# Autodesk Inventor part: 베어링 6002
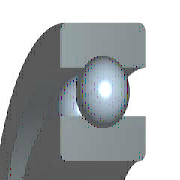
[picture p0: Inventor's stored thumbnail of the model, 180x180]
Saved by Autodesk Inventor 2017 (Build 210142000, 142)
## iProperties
IsCustomPart: 0
Created: 2012-02
Part Number: 베어링 6002
Material: 강철, 연강
Description: 깊은 그루브 볼 베어링
Document SubType Name: Modeling
Standard: KS B 2023
Designer: mduedu
Standards Organization: KS
Language: ko-KR
Size Designation: 6002 - 15 x 32 x 9
Categories: <MemberInstance><Categories><Category DisplayName="샤프트 부품" InternalName="7f7aeb1f-a693-4053-b835-cee3144e0d98" Mnemonic="SHFT"><Category DisplayName="베어링" Inter
Density: 7.86 g/cm^3
Mass: 29.8124 g
Surface Area: 39.9079 cm^2
Volume: 3.79293 cm^3
Appearance: 노란색
Author: mduedu
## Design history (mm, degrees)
sketch "스케치" dims "d0" = 4.42 (= -0.26 x WD + 0.26 x BD)
  geometry: L1 (2.29, 11.75)-(6.71, 11.75); L2 (4.5, 11.75)-(4.5, 9.54); L3 (4.5, 11.75)-(4.5, 13.96); L4 (2.858, 10.271)-(0, 10.271); L5 (0, 7.5)-(9, 7.5); L6 (2.858, 13.229)-(0, 13.229); L7 (0, 16)-(9, 16); L8 (9, 7.5)-(9, 10.271); L9 (6.142, 10.271)-(9, 10.271); L10 (6.142, 13.229)-(9, 13.229); L11 (9, 16)-(9, 13.229); L12 (-1.4, 0)-(8.4, 0) reference; L13 (0, -0.3)-(0, 5.3) reference
  constraints: 22 end point, 4 point on line, 2 collinear, 2 perpendicular, 2 symmetric about line, 1 midpoint, 1 parallel, 14 other
  dimensions: "d9" = 15 diameter of L5 L12 (= WD); "d11" = 32 diameter of L7 L12 (= BD); "d12" = 9 distance between parallel lines of L8 L13 (= KB); "d13" = 20.542 diameter of L9 L12 (= 0.326 x BD + 0.674 x WD)
revolve "본체" stored, may be unused: angle "d6" = 90 deg
revolve "볼" stored, may be unused: angle "d7" = 90 deg
pattern_circular "IDS_ARRAYBALL[SIMPL:T]" dims angle "d3" = 360 deg
body "Solid1"
fillet "모깎기1" dims "d1" = 0.3 (= KRS)
other parameters: "WD" = 15 [user parameter; used in 5 equation terms], "BD" = 32 [user parameter; used in 5 equation terms], "KB" = 9 [user parameter; used in 1 equation term], "KRS" = 0.3 [user parameter; used in 1 equation term], "d4" = 0, "d5" = 0, "d8" = 0, "d14" = 0, "d15" = 0, "BBA" = 0 [user parameter], "BC0" = 2850000 [user parameter], "BC" = 5590000 [user parameter], "BR" = 16 (= 0.5 x BD) [user parameter], "WR" = 7.5 (= 0.5 x WD) [user parameter]
